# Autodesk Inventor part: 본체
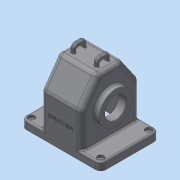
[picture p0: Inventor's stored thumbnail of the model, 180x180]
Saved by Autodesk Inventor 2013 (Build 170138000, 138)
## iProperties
Created: 2016-12
Part Number: 본체
Material: 일반
Document SubType Name: Modeling
Designer: dgall
Density: 1 g/cm^3
Author: dgall
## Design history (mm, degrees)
sketch "스케치1"
  geometry: L1 (0, 0)-(150, 0); L2 (150, 0)-(150, 110); L3 (150, 110)-(0, 110); L4 (0, 110)-(0, 0)
  constraints: 8 end point, 2 parallel, 1 horizontal, 1 perpendicular
  dimensions: "d0" = 150 distance of L2.end L3.end; "d2" = 110 distance of L1.end L2.end
extrude "돌출1" new body sketch "스케치1" distance "d3" = 15; taper "d4" = 0 deg
node "작업 평면1"
sketch "스케치2"
  geometry: L1 (0, 15)-(-110, 15) reference; L2 (0, 0)-(-110, 0) reference; L3 (-110, 15)-(-110, 80); L4 (-110, 80)-(-78.491, 125); L5 (-78.491, 125)-(-31.509, 125); L6 (-31.509, 125)-(0, 80); L7 (0, 80)-(0, 15)
  constraints: 10 end point, 2 vertical, 1 equal length, 1 perpendicular
  dimensions: "d6" = 35 deg angle of L3 L4; "d7" = 35 deg angle of L7 L6; "d8" = 125 distance between parallel lines of L2 L5; "d9" = 80 distance from line of L2 L6.end
extrude "돌출2" join sketch "스케치2" stored distance "d10" = 77; taper "d11" = 0 deg
sketch "스케치3"
  geometry: L1 (125, 31.509)-(125, 78.491) reference; L2 (0, 110)-(0, 0) reference; C1 r 37.5 at (65, 55); 1 further point
  constraints: 1 centre point, 1 horizontal alignment, 1 midpoint
  dimensions: "d12" = 65 distance from line of L2 C1.centre; "d13" = 75 diameter of C1
extrude "돌출3" join sketch "스케치3" distance "d14" = 5; taper "d15" = 0 deg
sketch "스케치4"
  geometry: L1 (-125, 78.491)-(-125, 31.509) reference; L2 (0, 0)-(0, 110) reference; C1 r 31 at (-65, 55); 2 further points
  constraints: 2 midpoint, 1 centre point, 1 horizontal alignment
  dimensions: "d16" = 62 diameter of C1; "d18" = 65 distance from line of L2 C1.centre
extrude "돌출4" join sketch "스케치4" distance "d19" = 10; taper "d20" = 0 deg
fillet "모깎기1" dims "d21" = 8
fillet "모깎기2" dims "d22" = 10
hole "구멍1" diameter "d31" = 5; stored, may be unused: countersink angle "d35" = 90 deg, drill point angle "d37" = 118 deg; dims "d29" = 10, "d30" = 10, "d32" = 6, "d33" = 12, "d34" = 5, "d36" = 8
hole "구멍2" diameter "d40" = 5; stored, may be unused: countersink angle "d44" = 90 deg, drill point angle "d46" = 118 deg; dims "d38" = 10, "d39" = 10, "d41" = 6, "d42" = 12, "d43" = 5, "d45" = 8
fillet "모깎기3" dims "d47" = 3
fillet "모깎기4" dims "d48" = 3
fillet "모깎기5" dims "d49" = 10
node "작업 평면3"
node "작업 평면4"
sketch "스케치8"
  geometry: L1 (-82.583, 1.808)-(-117, 25.908) reference; L2 (-125, 31.509)-(-125, 78.491) reference; L3 (-117, 25.908)-(-125, 31.509) reference; L4 (-125, 78.491)-(-117, 84.092) reference; L5 (-117, 84.092)-(-82.583, 108.192) reference; L6 (-78.424, 105)-(-114.132, 79.997); L7 (-114.132, 79.997)-(-120, 75.888); L8 (-120, 75.888)-(-120, 34.112); L9 (-120, 34.112)-(-114.132, 30.003); L10 (-114.132, 30.003)-(-78.424, 5); L11 (-78.424, 5)-(0, 5); L12 (-78.424, 105)-(0, 105); L13 (0, 105)-(0, 5); L14 (0, 10)-(0, 0) reference; L15 (-12, 0)-(-76.847, 0) reference; L16 (-76.847, 110)-(-12, 110) reference; 2 further points
  constraints: 16 end point, 2 perpendicular, 1 equal length, 1 midpoint, 1 parallel, 4 other
  dimensions: "d51" = 5 distance between parallel lines of L8 L2; "d53" = 5 distance between parallel lines of L15 L11; "d54" = 5 distance between parallel lines of L12 L16; "d55" = 4.10874 vertical distance of L6.end L7.end
extrude "돌출5" cut sketch "스케치8" stored distance "d56" = 67; taper "d57" = 0 deg
node "작업 평면5"
sketch "스케치9"
  geometry: L1 (21.5, 102.5)-(21.5, 27.5) reference; L2 (113.5, 34)-(113.5, 96) reference; L3 (21.5, 65)-(113.5, 65); L4 (98.5, 0)-(31.5, 0) reference; L5 (45.5, 65)-(45.5, 92); L6 (45.5, 92)-(31.5, 106); L7 (31.5, 106)-(31.5, 65); L8 (31.5, 120)-(31.5, 78.424) reference; 1 further point
  constraints: 8 end point, 3 perpendicular, 3 point on line, 2 midpoint
  dimensions: "d58" = 65 distance between parallel lines of L4 L3; "d59" = 45 deg angle of L5 L6; "d60" = 54 diameter of L5.end L3; "d61" = 24 distance between parallel lines of L1 L5
revolve "회전1" sketch "스케치9" stored, may be unused: angle "d63" = 90 deg
hole "구멍3" diameter "d66" = 40; stored, may be unused: countersink angle "d70" = 90 deg, drill point angle "d72" = 118 deg; dims "d64" = 10, "d65" = 10, "d67" = 6, "d68" = 12, "d69" = 5, "d71" = 8
chamfer "모따기1" distance "d75" = 1; stored, may be unused: second distance "d76" = 2, angle "d77" = 45 deg
fillet "모깎기8" dims "d78" = 3
fillet "모깎기9" dims "d79" = 3
node "작업 평면6"
sketch "스케치12"
  geometry: L1 (-78.491, 125)-(-31.509, 125) reference; L2 (-62.5, 125)-(-62.5, 132); L3 (-62.5, 132)-(-47.5, 132); L4 (-47.5, 132)-(-47.5, 125); L5 (-42.5, 125)-(-42.5, 140); L6 (-42.5, 140)-(-67.5, 140); L7 (-67.5, 140)-(-67.5, 125); L8 (-8, 0)-(-102, 0) reference; 4 further points
  constraints: 12 end point, 5 perpendicular, 4 point on line, 3 midpoint, 2 vertical alignment, 1 parallel
  dimensions: "d81" = 15 distance of L2.end L3.end; "d85" = 140 distance between parallel lines of L8 L6; "d86" = 25 distance of L5.end L6.end; "d87" = 8 distance between parallel lines of L3 L6
extrude "돌출6" join sketch "스케치12" distance "d88" = 8; taper "d89" = 0 deg
fillet "모깎기11" dims "d91" = 3
fillet "모깎기12" dims "d92" = 1
fillet "모깎기15" dims "d95" = 8, "d96" = 2, "d116" = 40
fillet "모깎기16" dims "d96" = 2
sketch "스케치13"
  geometry: C1 r 37.5 at (0, 0) reference; 2 further points
  constraints: 1 horizontal alignment
  dimensions: "d97" = 29 distance of C1.centre point (29, 0)
hole "구멍4" sketch "스케치13" at (29, 0) diameter "d98" = 2.459; stored, may be unused: countersink angle "d102" = 90 deg, drill point angle "d104" = 118 deg; dims "d99" = 6, "d100" = 12, "d101" = 5, "d103" = 8
sketch "스케치14"
  geometry: C1 r 31 at (0, 0) reference; 2 further points
  constraints: 1 horizontal alignment
  dimensions: "d108" = 26 distance of point (-26, 0) C1.centre
hole "구멍5" sketch "스케치14" at (-26, 0) diameter "d109" = 2.459; stored, may be unused: countersink angle "d113" = 90 deg, drill point angle "d115" = 118 deg; dims "d110" = 6, "d111" = 12, "d112" = 5, "d114" = 8
sketch "스케치15"
  geometry: L1 (0, 0)-(130, 0) reference; 3 further points
  constraints: 1 midpoint, 1 vertical alignment, 1 other
  dimensions: "d120" = 45 distance from line of L1 point (65, 45)
feature "엠보싱1" sketch "스케치15" dims "d121" = 0.5, "d122" = 0
fillet "모깎기18" dims "d123" = 10
fillet "모깎기19" dims "d124" = 10
fillet "모깎기20" dims "d125" = 3
node "솔리드1"
mirror "대칭1"
mirror "대칭2"
pattern_circular "원형 패턴1" dims angle "d106" = 360 deg
pattern_circular "원형 패턴2" dims angle "d117" = 360 deg
other parameters: "d80" = -18
